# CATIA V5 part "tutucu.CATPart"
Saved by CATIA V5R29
Part number: tutucu
Revision: HERHANG?
Definition: B??MEYEN
Nomenclature: tutucu
Source: Unknown
Bounding box of the stored display mesh (mm): x -579.422 to -391.883, y -310.528 to 310.528, z -100 to 77.537
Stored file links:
  C:\가치같이\SmartFactory_Freeze dryer\tutucu.CATPart
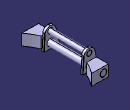
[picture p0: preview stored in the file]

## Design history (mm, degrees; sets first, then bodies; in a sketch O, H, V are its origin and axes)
Body1 "Kes-Ekstr?yon3" (main body)
  Solid1: solid without history
Body2 "Kes-Ekstr?yon4"
  Solid2: solid without history
Body3 "Radyus4"
  Solid3: solid without history
Body4 "Aynalama2"
  Solid4: solid without history
Body5 "Y?seklik-Ekstr?yon9"
  Solid5: solid without history
Body6 "Y?seklik-Ekstr?yon10"
  Solid6: solid without history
